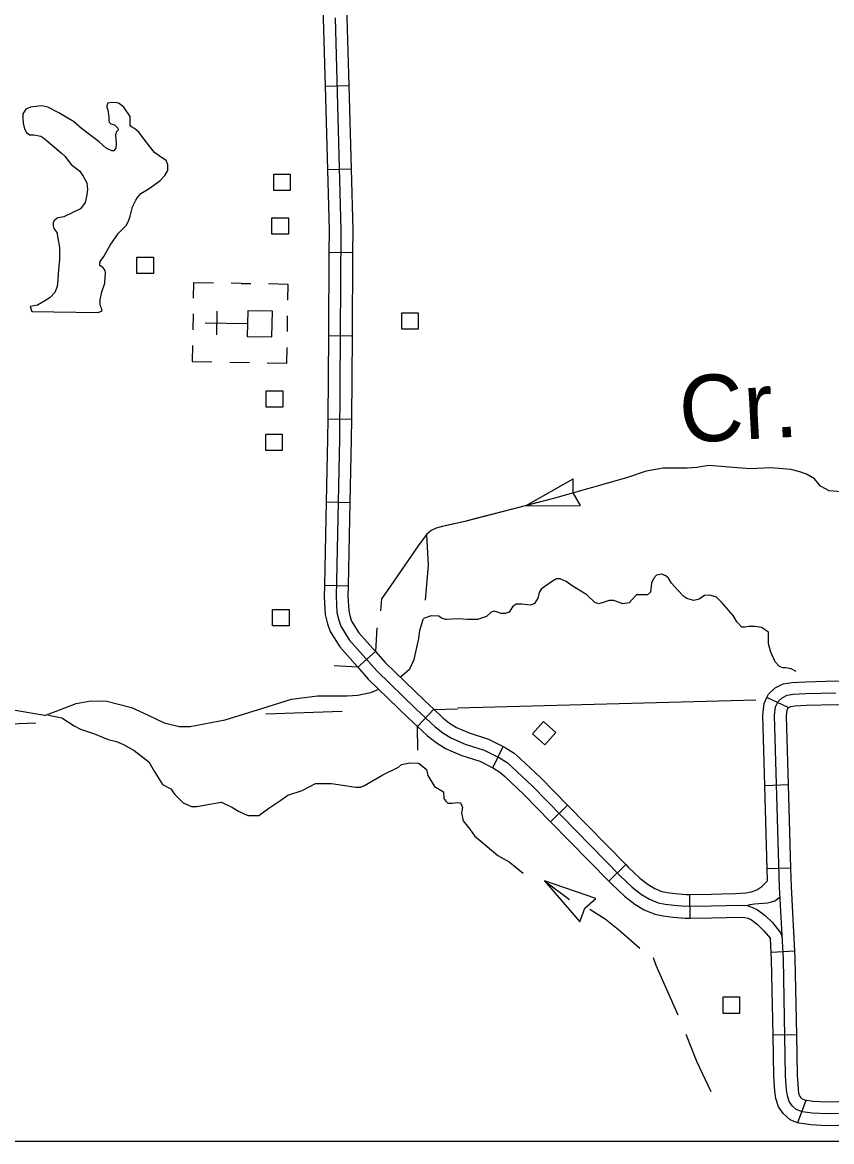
# Model space of a CAD drawing. Extents: x 155 to 3386, y 68 to 2138.
# Drawn here: x 1365.4 to 1512, y 348.6 to 551.2 of the extents above; entities that cross this region are included whole.
import ezdxf

# ---------------------------------------------------------------- set-up
doc = ezdxf.new("R2010")
doc.units = 0
for name, color, linetype in [('Default', 7, 'Continuous'), ('E_No Plot', 7, 'Continuous'), ('Level 32', 7, 'Continuous'), ('Level 35', 7, 'Continuous'), ('Level 38', 7, 'Continuous'), ('Level 43', 7, 'Continuous'), ('Level 5', 7, 'Continuous'), ('Level 56', 7, 'Continuous'), ('Level 57', 7, 'Continuous')]:
    doc.layers.add(name, color=color, linetype=linetype)

msp = doc.modelspace()

# ---------------------------------------------------------------- linework, layer by layer
at = {"layer": 'Default'}
msp.add_lwpolyline([(1150.5, 1308.99), (2342.15, 1308.99), (2342.15, 348.58), (1150.5, 348.58)], close=True, dxfattribs=at)
at = {"layer": 'E_No Plot'}
msp.add_lwpolyline([(1150.5, 1308.99), (2342.15, 1308.99), (2342.15, 348.58), (1150.5, 348.58)], close=True, dxfattribs=at)
msp.add_lwpolyline([(1150.5, 1308.99), (2342.15, 1308.99), (2342.15, 348.58), (1150.5, 348.58)], close=True, dxfattribs=at)
at = {"layer": 'Level 32'}
for p, q in [((1420.23, 539.71), (1424.51, 539.83)), ((1420.65, 524.63), (1424.93, 524.75)), ((1420.92, 509.62), (1425.21, 509.59)), ((1420.81, 494.54), (1425.1, 494.51)), ((1420.7, 479.45), (1424.99, 479.42)), ((1420.43, 464.4), (1424.71, 464.31)), ((1420.1, 449.32), (1424.39, 449.23)), ((1426.13, 434.49), (1429.34, 437.33)), ((1504.13, 427.18), (1500.25, 428.99)), ((1436.98, 423.73), (1439.9, 426.86)), ((1450.61, 416.29), (1452.5, 420.14)), ((1504.15, 413.16), (1499.87, 413.03)), ((1461.07, 406.51), (1464.13, 409.51)), ((1471.62, 395.73), (1474.69, 398.73)), ((1504.59, 398.08), (1500.31, 397.95)), ((1486.37, 389.07), (1486.32, 393.35)), ((1505.33, 383.07), (1501.05, 382.83)), ((1505.66, 367.91), (1501.37, 367.83)), ((1507.31, 356.03), (1505.81, 352.01))]:
    msp.add_line(p, q, dxfattribs=at)
for points in [[(1419.78, 554.76), (1419.89, 551.97), (1420.23, 539.71)], [(1424.06, 554.93), (1424.17, 552.12), (1424.51, 539.83)], [(1422.03, 552.04), (1423.1, 513.6), (1422.82, 475.82), (1422.2, 447.28), (1422.37, 444.37), (1422.7, 442.97), (1423.1, 441.9), (1424.61, 439.44), (1429.58, 433.82), (1436.74, 426.88), (1440.15, 423.69), (1441.55, 422.58), (1443.01, 421.68), (1445.58, 420.56), (1449.05, 419.44), (1451.79, 418.1), (1453.19, 417.2), (1454.19, 416.31), (1457.73, 412.98), (1473.62, 396.75), (1475.86, 394.63), (1477.54, 393.34), (1478.99, 392.46), (1480.59, 391.84), (1481.82, 391.56), (1483.47, 391.37), (1485.54, 391.2), (1490.18, 391.26), (1495.69, 391.37), (1496.67, 391.31), (1497.56, 391.03), (1498.57, 390.56), (1499.94, 389.52), (1501.25, 388.23), (1502.15, 387.2), (1502.57, 386.64), (1502.85, 386.16), (1503.05, 385.49)], [(1420.23, 539.71), (1420.65, 524.63)], [(1424.51, 539.83), (1424.93, 524.75)], [(1420.65, 524.63), (1420.95, 513.57), (1420.92, 509.62)], [(1424.93, 524.75), (1425.24, 513.62), (1425.21, 509.59)], [(1420.92, 509.62), (1420.81, 494.54)], [(1425.21, 509.59), (1425.1, 494.51)], [(1420.81, 494.54), (1420.7, 479.45)], [(1425.1, 494.51), (1424.99, 479.42)], [(1420.7, 479.45), (1420.67, 475.85), (1420.43, 464.4)], [(1424.99, 479.42), (1424.96, 475.79), (1424.71, 464.31)], [(1420.43, 464.4), (1420.1, 449.32)], [(1424.71, 464.31), (1424.39, 449.23)], [(1420.1, 449.32), (1420.06, 447.24), (1420.24, 444.05), (1420.65, 442.35), (1421.16, 440.96), (1422.88, 438.16), (1426.13, 434.49)], [(1424.39, 449.23), (1424.34, 447.32), (1424.5, 444.68), (1424.76, 443.59), (1425.03, 442.84), (1426.33, 440.72), (1429.34, 437.33)], [(1429.34, 437.33), (1431.13, 435.31), (1438.22, 428.44), (1439.9, 426.86)], [(1426.13, 434.49), (1428.03, 432.34), (1435.27, 425.33), (1436.98, 423.73)], [(1500.25, 428.99), (1500.53, 429.6), (1501.78, 430.73), (1503.23, 431.46), (1504.76, 431.73), (1507.25, 431.86), (1512.76, 432), (1516.32, 431.93), (1516.83, 431.91)], [(1572.8, 355.16), (1511.15, 353.61), (1508.44, 353.74), (1506.62, 354), (1505.59, 354.39), (1504.88, 355.03), (1504.29, 355.87), (1503.97, 356.85), (1503.84, 357.95), (1503.65, 360.53), (1503.26, 381.63), (1502.55, 394.64), (1501.64, 425.71), (1501.84, 427.33), (1502.29, 428.3), (1503, 428.95), (1503.91, 429.4), (1505.01, 429.59), (1507.34, 429.72), (1512.77, 429.85)], [(1499.87, 413.03), (1499.5, 425.81), (1499.75, 427.92), (1500.25, 428.99)], [(1504.05, 427), (1504.22, 427.16), (1504.59, 427.34), (1505.25, 427.46), (1507.42, 427.58), (1512.78, 427.71), (1516.2, 427.65), (1516.68, 427.63)], [(1439.9, 426.86), (1441.56, 425.32), (1442.79, 424.33), (1444, 423.58), (1446.34, 422.57), (1449.85, 421.43), (1452.5, 420.14)], [(1504.15, 413.16), (1503.79, 425.61), (1503.92, 426.73), (1504.13, 427.18)], [(1436.98, 423.73), (1438.75, 422.07), (1440.32, 420.82), (1442.01, 419.78), (1444.82, 418.55), (1448.24, 417.45), (1450.61, 416.29)], [(1452.5, 420.14), (1452.84, 419.97), (1454.49, 418.92), (1455.64, 417.89), (1459.23, 414.52), (1464.13, 409.51)], [(1450.61, 416.29), (1450.74, 416.23), (1451.89, 415.49), (1452.75, 414.73), (1456.23, 411.45), (1461.07, 406.51)], [(1500.31, 397.95), (1499.87, 413.03)], [(1504.59, 398.08), (1504.15, 413.16)], [(1464.13, 409.51), (1474.69, 398.73)], [(1461.07, 406.51), (1471.62, 395.73)], [(1474.69, 398.73), (1475.12, 398.28), (1477.25, 396.26), (1478.75, 395.11), (1479.94, 394.39), (1481.21, 393.9), (1482.18, 393.68), (1483.68, 393.5), (1485.61, 393.34), (1486.32, 393.35)], [(1500.37, 395.81), (1500.31, 397.95)], [(1505.33, 383.07), (1504.69, 394.73), (1504.59, 398.08)], [(1471.62, 395.73), (1472.12, 395.23), (1474.46, 393), (1476.32, 391.57), (1478.04, 390.53), (1479.96, 389.79), (1481.45, 389.45), (1483.25, 389.24), (1485.46, 389.06), (1486.37, 389.07)], [(1494.55, 393.48), (1496.44, 393.62), (1497.46, 393.84), (1498.42, 394.16), (1499.34, 394.78), (1500.37, 395.81)], [(1486.32, 393.35), (1490.14, 393.4), (1492.03, 393.44), (1494.55, 393.48)], [(1496.67, 391.31), (1497.23, 391.51), (1498.04, 391.65), (1500.36, 391.82), (1501.11, 391.98), (1501.7, 392.18), (1502.2, 392.52), (1502.48, 392.8), (1502.64, 392.99)], [(1486.37, 389.07), (1490.21, 389.11), (1495.65, 389.22), (1496.28, 389.19), (1496.78, 389.03), (1497.45, 388.71), (1498.54, 387.89), (1499.15, 387.3)], [(1499.15, 387.3), (1499.69, 386.77), (1500.91, 385.36)], [(1501.05, 382.83), (1500.91, 385.36)], [(1505.66, 367.91), (1505.4, 381.71), (1505.33, 383.07)], [(1501.37, 367.83), (1501.12, 381.56), (1501.05, 382.83)], [(1505.81, 352.01), (1504.45, 352.52), (1503.25, 353.61), (1502.36, 354.91), (1501.87, 356.38), (1501.71, 357.74), (1501.51, 360.43), (1501.37, 367.83)], [(1507.31, 356.03), (1506.73, 356.25), (1506.5, 356.45), (1506.23, 356.84), (1506.07, 357.31), (1505.98, 358.15), (1505.79, 360.63), (1505.66, 367.91)], [(1521.56, 356.02), (1511.18, 355.75), (1508.64, 355.87), (1507.16, 356.09), (1507.31, 356.03)], [(1521.67, 351.73), (1511.13, 351.47), (1508.23, 351.6), (1506.09, 351.91), (1505.81, 352.01)]]:
    msp.add_lwpolyline(points, dxfattribs=at)
at = {"layer": 'Level 35'}
for points in [[(1379.82, 498.99), (1379.69, 499.5), (1379.52, 499.88), (1379.48, 500.26), (1379.48, 500.98), (1379.78, 502.46), (1380.33, 503.99), (1380.37, 505.04), (1380.45, 505.85), (1380.37, 506.31), (1379.99, 506.78), (1379.44, 507.2), (1379.44, 507.54), (1379.48, 507.96), (1380.12, 508.85), (1381.3, 510.93), (1382.82, 513.08), (1384.26, 514.52), (1384.68, 515.41), (1384.89, 516.17), (1385.32, 517.83), (1385.95, 519.06), (1386.21, 519.52), (1386.84, 520.24), (1388.36, 521.17), (1390.27, 522.57), (1391.2, 523.54), (1391.75, 524.39), (1391.75, 525.02), (1391.75, 525.53), (1391.45, 526.25), (1390.6, 526.76), (1389.34, 527.69), (1387.73, 529.68), (1386.54, 531.29), (1385.7, 532.01), (1385.15, 532.3), (1384.94, 532.6), (1384.89, 532.94), (1384.89, 534.21), (1383.79, 535.86), (1383.2, 536.32), (1382.82, 536.62), (1382.48, 536.66), (1381.6, 536.75), (1380.83, 536.62), (1380.75, 536.24), (1380.71, 536.2), (1380.71, 535.81), (1380.88, 535.43), (1381, 534.54), (1381.05, 534.08), (1381.05, 533.53), (1381.13, 533.15), (1381.43, 532.85), (1382.06, 532.68), (1382.65, 532.09), (1382.74, 531.71), (1382.4, 531.37), (1382.27, 530.82), (1382.36, 529.3), (1382.31, 528.49), (1381.98, 527.99), (1381.6, 527.99), (1380.54, 528.45), (1379.27, 529.59), (1376.1, 532.01), (1374.62, 533.32), (1372, 534.84), (1370.01, 535.86), (1368.91, 536.15), (1368.32, 536.07), (1366.84, 535.86), (1366.03, 535.52), (1365.48, 534.67), (1365.44, 533.91), (1365.52, 532.98), (1365.74, 531.96), (1366.16, 531.29), (1366.71, 530.86), (1367.47, 530.86), (1368.74, 530.65), (1369.29, 530.27), (1371.57, 528.37), (1372.5, 527.56), (1373.09, 527.01), (1374.24, 525.53), (1375.72, 524.35), (1376.39, 523.37), (1377.07, 522.19), (1377.16, 521), (1377.07, 519.99), (1376.77, 518.64), (1375.89, 517.45), (1374.66, 516.86), (1372.88, 516.01), (1371.83, 515.84), (1371.15, 515.38), (1370.98, 514.95), (1370.94, 514.4), (1371.11, 513.94)], [(1371.11, 513.94), (1371.61, 513.18), (1371.83, 512.19), (1372.12, 510.5), (1372.08, 508.26), (1371.95, 506.52), (1371.83, 504.66), (1371.7, 503.43), (1371.28, 502.33), (1370.39, 501.4), (1369.29, 500.72), (1368.15, 500.05), (1366.79, 499.8)], [(1366.79, 499.8), (1367.09, 498.91), (1379.14, 498.7), (1379.82, 498.99)], [(1504.63, 434.18), (1503.65, 434.39), (1503.15, 434.39), (1502.55, 434.6), (1501.78, 435.45), (1501, 437.21), (1500.58, 438.73), (1500.55, 440), (1500.55, 440.81), (1499.31, 441.69), (1498.12, 441.83), (1496.99, 441.83), (1496.29, 441.76), (1495.69, 441.76), (1494.84, 442.71), (1494.14, 443.84), (1492.06, 446.23), (1491.14, 447.19), (1489.91, 447.54), (1488.96, 447.47), (1487.97, 446.8), (1487.02, 446.55), (1485.75, 446.94), (1485.22, 447.29), (1484.06, 448.49), (1482.97, 449.69), (1482.44, 450.6), (1481.98, 451.03), (1481.17, 451.34), (1480.26, 451.13), (1479.77, 450.6), (1479.34, 449.72), (1479.17, 448.1), (1478.64, 447.61), (1477.76, 447.57), (1476.63, 447.57), (1475.79, 446.66), (1475.29, 446.13), (1474.16, 445.95), (1472.51, 446.55), (1471.7, 446.55), (1470.75, 446.27), (1469.8, 445.95), (1469.06, 446.2), (1467.61, 447.61), (1465.01, 449.23), (1463.88, 450), (1462.82, 450.46), (1462.12, 450.5), (1461.41, 450.08), (1460.01, 449.09), (1459.34, 448.63), (1459.02, 448.03), (1458.74, 446.97), (1458.14, 445.99), (1457.43, 445.74), (1455.88, 445.88), (1454.83, 445.92), (1454.19, 445.39), (1453.59, 444.47), (1452.85, 444.19), (1452.12, 444.23), (1451.48, 444.47), (1450.85, 444.65), (1450.28, 444.44), (1449.47, 443.66), (1447.82, 443.13), (1446.02, 443.13), (1444.4, 443.27), (1442.15, 443.1), (1442.04, 443.13), (1441.3, 443.34), (1440.84, 443.7), (1439.43, 443.77), (1438.06, 443.31)], [(1433.82, 432.7), (1435.55, 434.17), (1436.35, 435.85), (1437.23, 439.66), (1437.41, 441.16), (1438.06, 443.31)], [(1369.48, 425.73), (1375.14, 427.89), (1377.8, 428.42), (1380.71, 428.33), (1385.14, 427.18), (1388.06, 425.85), (1391.06, 424.44), (1393.8, 423.73), (1395.75, 423.73), (1402.12, 424.97), (1408.93, 427.09), (1414.15, 428.69), (1418.84, 429.3), (1421.58, 429.3), (1424.23, 429.3), (1426.18, 429.39), (1428.12, 429.84), (1428.48, 429.92), (1429.93, 430.5)], [(1369.48, 425.73), (1362.64, 426.88)], [(1370.14, 425.78), (1372.54, 425.32), (1374.75, 423.89), (1375.92, 423.28), (1378.44, 422.41), (1380.95, 421.37), (1382.43, 421.03), (1383.73, 420.46), (1385.64, 419.42), (1388.28, 417.34), (1389.23, 415.65), (1390.75, 413.22), (1392.27, 412.44), (1393.01, 411.44), (1394.52, 409.92), (1396, 409.27), (1396.99, 409.27), (1398.64, 409.58), (1401.46, 410.05), (1403.45, 409.1), (1404.54, 408.4), (1406.21, 407.62), (1408.24, 407.62), (1410.02, 408.97), (1412.19, 410.4), (1413.49, 411.31), (1416.09, 412.18), (1418.48, 413.44), (1421.38, 413.44), (1425.8, 412.74), (1426.71, 412.74), (1427.36, 413.05)], [(1427.36, 413.05), (1430.69, 414.98), (1433.51, 416.37), (1434.08, 416.89), (1435.55, 417.15), (1437.11, 417.11), (1437.24, 417.06), (1438.59, 415.94), (1438.85, 414.85), (1440.06, 412.9), (1441.66, 411.9), (1441.75, 410.73), (1442.1, 410.25), (1442.44, 409.86), (1443.18, 409.86), (1444.26, 409.99), (1444.74, 409.91), (1445.09, 409.08), (1444.96, 408.09), (1445.26, 406.65), (1446.43, 405.14), (1447.3, 403.96), (1451.53, 400.39), (1453.56, 399.22), (1456.12, 397.19)]]:
    msp.add_lwpolyline(points, dxfattribs=at)
at = {"layer": 'Level 38'}
for points in [[(1429.59, 441.61), (1429.34, 437.33)], [(1426.13, 434.49), (1421.85, 434.75)], [(1439.93, 426.84), (1444.21, 426.92)], [(1437.03, 419.47), (1436.95, 423.76)]]:
    msp.add_lwpolyline(points, dxfattribs=at)
at = {"layer": 'Level 43'}
for p, q in [((1456.64, 463.76), (1465.17, 468.6)), ((1465.09, 468.67), (1465.13, 466.06)), ((1466.47, 463.79), (1465.14, 466.03)), ((1456.64, 463.76), (1466.45, 463.69)), ((1469.24, 392.59), (1459.97, 395.79)), ((1459.97, 395.79), (1466.4, 388.38)), ((1467.27, 390.88), (1469.24, 392.59)), ((1466.4, 388.38), (1467.25, 390.85))]:
    msp.add_line(p, q, dxfattribs=at)
for points in [[(1523.08, 465.5), (1511.51, 466.39), (1510.89, 466.79), (1509.99, 467.28), (1508.88, 468.57), (1507.41, 469.46), (1506.21, 469.86), (1504.61, 470.26), (1500.96, 470.57), (1497.22, 470.39), (1492.68, 470.75), (1489.74, 471.02), (1487.56, 470.66), (1485.74, 470.53), (1483.51, 470.53), (1481.46, 470.53), (1478.39, 469.99), (1474.83, 468.79), (1461.61, 465.05), (1445.55, 460.87), (1441.67, 460.02), (1440.34, 459.66), (1439.45, 459.22), (1438.6, 458.51), (1437.09, 456.46), (1431.48, 448.31), (1430.46, 446.84), (1430.24, 444.66)], [(1482.11, 470.53), (1481.46, 470.53), (1478.39, 469.99), (1474.83, 468.79), (1471.19, 467.76)], [(1497.14, 470.4), (1492.68, 470.75), (1489.74, 471.02), (1487.56, 470.66), (1485.88, 470.54)], [(1511.09, 466.66), (1510.89, 466.79), (1509.99, 467.28), (1508.88, 468.57), (1507.41, 469.46), (1506.21, 469.86), (1504.61, 470.26), (1500.96, 470.57), (1500.91, 470.57)], [(1467.56, 466.73), (1461.61, 465.05), (1456.64, 463.76)], [(1452.99, 462.8), (1447.52, 461.38)], [(1447.52, 461.38), (1445.55, 460.87), (1442.01, 460.09)], [(1438.61, 458.46), (1438.87, 452.97), (1438.34, 446.6)], [(1505.58, 433.72), (1504.63, 434.18)], [(1459.97, 395.79), (1464.5, 392.4)], [(1468.19, 390.69), (1470.95, 388.9), (1473.36, 386.96), (1477.26, 383.6)], [(1479.63, 381.89), (1480.16, 380.55), (1484.14, 371.51)], [(1485.56, 368.02), (1487.51, 363.15), (1490.08, 357.65)]]:
    msp.add_lwpolyline(points, dxfattribs=at)
at = {"layer": 'Level 5'}
for points in [[(1444.22, 427.12), (1498.23, 428.59)], [(1409.5, 426.02), (1423.32, 426.55)], [(1270.42, 420.67), (1367.82, 424.42)]]:
    msp.add_lwpolyline(points, dxfattribs=at)
at = {"layer": 'Level 56'}
for points in [[(1410.93, 520.81), (1410.93, 523.78), (1413.92, 523.78), (1413.92, 520.81)], [(1410.58, 512.88), (1410.58, 515.86), (1413.57, 515.86), (1413.57, 512.88)], [(1386.13, 505.74), (1386.13, 508.72), (1389.11, 508.72), (1389.11, 505.74)], [(1434.1, 495.68), (1434.1, 498.65), (1437.08, 498.65), (1437.08, 495.68)], [(1409.56, 481.58), (1409.56, 484.55), (1412.54, 484.55), (1412.54, 481.58)], [(1409.46, 473.72), (1409.46, 476.69), (1412.45, 476.69), (1412.45, 473.72)], [(1410.71, 441.95), (1410.71, 444.92), (1413.69, 444.92), (1413.69, 441.95)], [(1459.79, 424.65), (1462, 422.67), (1460.01, 420.45), (1457.8, 422.43)], [(1492.32, 371.81), (1492.32, 374.78), (1495.31, 374.78), (1495.31, 371.81)]]:
    msp.add_lwpolyline(points, close=True, dxfattribs=at)
at = {"layer": 'Level 57'}
for p, q in [((1404.99, 503.97), (1403.23, 504)), ((1404.99, 503.97), (1406.8, 503.93)), ((1400.59, 494.68), (1400.67, 498.96)), ((1396.3, 498.44), (1396.25, 495.58)), ((1398.49, 496.86), (1406.18, 496.71)), ((1413.39, 495.24), (1413.44, 498.1)), ((1402.94, 489.72), (1406.51, 489.65))]:
    msp.add_line(p, q, dxfattribs=at)
for points in [[(1396.36, 501.28), (1396.42, 504.14), (1399.99, 504.07)], [(1413.5, 500.94), (1413.56, 503.8), (1409.98, 503.87)], [(1396.19, 492.71), (1396.13, 489.85), (1399.71, 489.78)], [(1409.7, 489.59), (1413.27, 489.52), (1413.33, 492.37)]]:
    msp.add_lwpolyline(points, dxfattribs=at)
msp.add_lwpolyline([(1410.68, 498.93), (1406.22, 499.02), (1406.13, 494.39), (1410.59, 494.3)], close=True, dxfattribs=at)

# ---------------------------------------------------------------- texts
at = {"layer": 'Level 35'}
msp.add_text('Cr.', height=12.069, rotation=3.0641, dxfattribs=at).set_placement((1484.66, 475.09))

doc.saveas('drawing.dxf')
